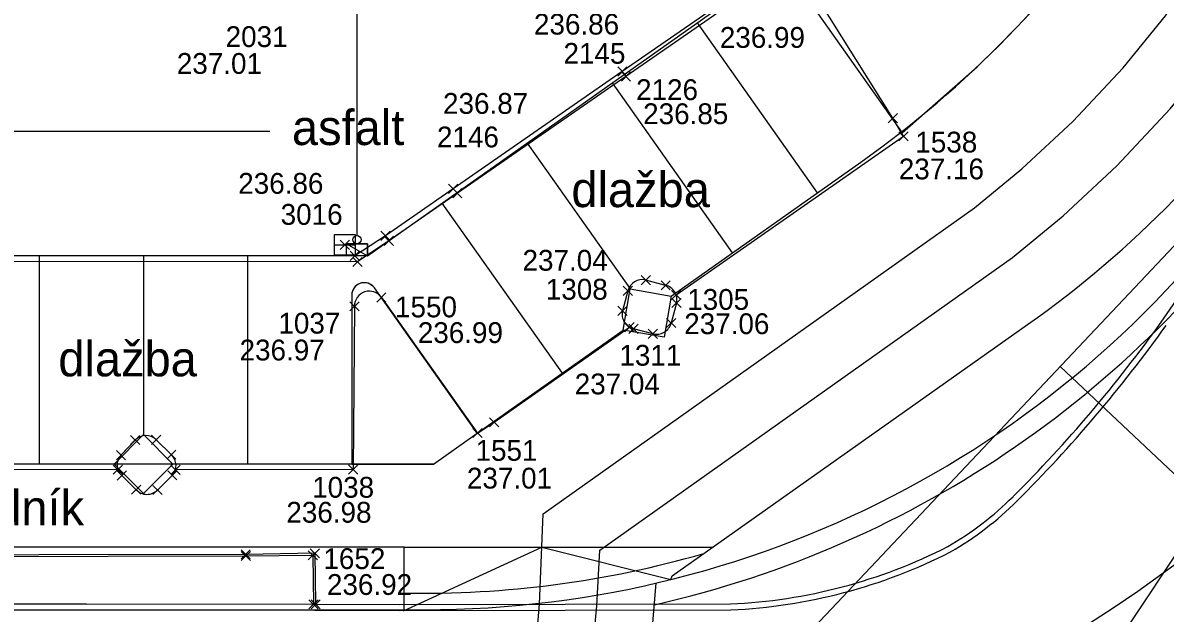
# Model space of a CAD drawing. Extents: x -264165 to -263733, y -1242319 to -1242245.
# Drawn here: x -263825.46 to -263798.04, y -1242301.57 to -1242287.38 of the extents above; entities that cross this region are included whole.
import ezdxf

# ---------------------------------------------------------------- set-up
doc = ezdxf.new("R2010")
doc.units = 0
for name, color, linetype in [('KFA_BOD_CISLO', 7, 'Continuous'), ('KFA_BOD_SYMBOL', 7, 'Continuous'), ('KFA_BOD_VYSKA', 7, 'Continuous'), ('KFA_SO_20-2_OBRUBNIKY_DOLNA_HRANA', 7, 'Continuous'), ('KFA_SO_20-2_OBRUBNIKY_HORNA_HRANA', 7, 'Continuous'), ('KFA_UV_BOD_CISLO', 7, 'Continuous'), ('KFA_UV_BOD_SYMBOL', 7, 'Continuous'), ('KFA_UV_BOD_VYSKA', 7, 'Continuous'), ('POPIS', 7, 'Continuous'), ('PROJEKT_OBRUBNIKY_KOMUNIKACIE', 7, 'Continuous'), ('PROJEKT_TDZ_VODOROVNE', 7, 'Continuous'), ('SITUACIA_DSP_2D', 7, 'Continuous'), ('SO_20-1_OBRUBNIKY_DOLNA_HRANA', 7, 'Continuous'), ('SO_20-1_OBRUBNIKY_HORNA_HRANA', 7, 'Continuous'), ('ULICNA_VPUST_POKLOP', 7, 'Continuous')]:
    doc.layers.add(name, color=color, linetype=linetype)

msp = doc.modelspace()

# ---------------------------------------------------------------- linework, layer by layer
at = {"layer": 'KFA_BOD_SYMBOL'}
for p, q in [((-263811.183, -1242288.666), (-263810.962, -1242288.444)), ((-263810.962, -1242288.666), (-263811.183, -1242288.444)), ((-263811.095, -1242288.784), (-263810.875, -1242288.562)), ((-263810.875, -1242288.784), (-263811.095, -1242288.562)), ((-263804.688, -1242289.786), (-263804.467, -1242289.566)), ((-263804.467, -1242289.786), (-263804.688, -1242289.566)), ((-263804.431, -1242290.221), (-263804.209, -1242289.999)), ((-263804.209, -1242290.221), (-263804.431, -1242289.999)), ((-263815.243, -1242291.48), (-263815.022, -1242291.258)), ((-263815.022, -1242291.48), (-263815.243, -1242291.258)), ((-263815.143, -1242291.589), (-263814.921, -1242291.367)), ((-263814.921, -1242291.589), (-263815.143, -1242291.367)), ((-263816.87, -1242292.612), (-263816.649, -1242292.39)), ((-263816.649, -1242292.612), (-263816.87, -1242292.39)), ((-263816.789, -1242292.73), (-263816.568, -1242292.508)), ((-263816.568, -1242292.73), (-263816.789, -1242292.508)), ((-263817.603, -1242293.093), (-263817.382, -1242292.872)), ((-263817.382, -1242293.093), (-263817.603, -1242292.872)), ((-263817.541, -1242293.24), (-263817.32, -1242293.019)), ((-263817.32, -1242293.24), (-263817.541, -1242293.019)), ((-263810.617, -1242293.674), (-263810.395, -1242293.453)), ((-263810.395, -1242293.674), (-263810.617, -1242293.453)), ((-263810.142, -1242293.802), (-263809.921, -1242293.582)), ((-263809.921, -1242293.802), (-263810.142, -1242293.582)), ((-263811.049, -1242293.934), (-263810.828, -1242293.714)), ((-263810.828, -1242293.934), (-263811.049, -1242293.714)), ((-263809.889, -1242294.032), (-263809.668, -1242293.811)), ((-263809.668, -1242294.032), (-263809.889, -1242293.811)), ((-263817.611, -1242294.303), (-263817.39, -1242294.083)), ((-263817.39, -1242294.303), (-263817.611, -1242294.083)), ((-263816.968, -1242294.092), (-263816.747, -1242293.87)), ((-263816.747, -1242294.092), (-263816.968, -1242293.87)), ((-263809.881, -1242294.225), (-263809.66, -1242294.005)), ((-263809.66, -1242294.225), (-263809.881, -1242294.005)), ((-263811.177, -1242294.416), (-263810.955, -1242294.194)), ((-263810.955, -1242294.416), (-263811.177, -1242294.194)), ((-263811.008, -1242294.808), (-263810.787, -1242294.586)), ((-263810.787, -1242294.808), (-263811.008, -1242294.586)), ((-263810.913, -1242294.845), (-263810.692, -1242294.623)), ((-263810.692, -1242294.845), (-263810.913, -1242294.623)), ((-263810.011, -1242294.704), (-263809.79, -1242294.484)), ((-263809.79, -1242294.704), (-263810.011, -1242294.484)), ((-263810.448, -1242294.964), (-263810.226, -1242294.742)), ((-263810.226, -1242294.964), (-263810.448, -1242294.742)), ((-263814.258, -1242297.092), (-263814.036, -1242296.87)), ((-263814.036, -1242297.092), (-263814.258, -1242296.87)), ((-263814.661, -1242297.349), (-263814.44, -1242297.127)), ((-263814.44, -1242297.349), (-263814.661, -1242297.127)), ((-263822.877, -1242297.516), (-263822.655, -1242297.296)), ((-263822.655, -1242297.516), (-263822.877, -1242297.296)), ((-263822.376, -1242297.512), (-263822.155, -1242297.291)), ((-263822.155, -1242297.512), (-263822.376, -1242297.291)), ((-263823.219, -1242297.88), (-263822.997, -1242297.659)), ((-263822.997, -1242297.88), (-263823.219, -1242297.659)), ((-263822.009, -1242297.869), (-263821.788, -1242297.647)), ((-263821.788, -1242297.869), (-263822.009, -1242297.647)), ((-263823.294, -1242298.228), (-263823.073, -1242298.007)), ((-263823.073, -1242298.228), (-263823.294, -1242298.007)), ((-263823.199, -1242298.372), (-263822.978, -1242298.15)), ((-263822.978, -1242298.372), (-263823.199, -1242298.15)), ((-263821.986, -1242298.366), (-263821.765, -1242298.144)), ((-263821.765, -1242298.366), (-263821.986, -1242298.144)), ((-263821.911, -1242298.231), (-263821.69, -1242298.011)), ((-263821.69, -1242298.231), (-263821.911, -1242298.011)), ((-263817.645, -1242298.225), (-263817.424, -1242298.004)), ((-263817.424, -1242298.225), (-263817.645, -1242298.004)), ((-263822.855, -1242298.71), (-263822.633, -1242298.488)), ((-263822.633, -1242298.71), (-263822.855, -1242298.488)), ((-263822.345, -1242298.718), (-263822.123, -1242298.497)), ((-263822.123, -1242298.718), (-263822.345, -1242298.497)), ((-263820.225, -1242300.264), (-263820.003, -1242300.042)), ((-263820.003, -1242300.264), (-263820.225, -1242300.042)), ((-263820.223, -1242300.303), (-263820.002, -1242300.083)), ((-263820.002, -1242300.303), (-263820.223, -1242300.083)), ((-263818.615, -1242300.288), (-263818.394, -1242300.066)), ((-263818.394, -1242300.288), (-263818.615, -1242300.066)), ((-263818.565, -1242300.238), (-263818.344, -1242300.016)), ((-263818.344, -1242300.238), (-263818.565, -1242300.016)), ((-263818.596, -1242301.463), (-263818.375, -1242301.242)), ((-263818.375, -1242301.463), (-263818.596, -1242301.242)), ((-263818.546, -1242301.463), (-263818.325, -1242301.242)), ((-263818.325, -1242301.463), (-263818.546, -1242301.242))]:
    msp.add_line(p, q, dxfattribs=at)
at = {"layer": 'KFA_SO_20-2_OBRUBNIKY_DOLNA_HRANA'}
for points in [[(-263806.994, -1242271.026), (-263807.002, -1242275.743), (-263807.011, -1242281.745), (-263807.02, -1242285.741), (-263807.029, -1242285.754), (-263811.073, -1242288.555), (-263815.133, -1242291.369), (-263816.759, -1242292.501), (-263817.492, -1242292.982)], [(-263806.84, -1242270.884), (-263806.855, -1242275.745), (-263806.866, -1242281.754), (-263806.878, -1242285.825), (-263810.985, -1242288.673), (-263815.032, -1242291.478), (-263816.678, -1242292.619), (-263817.431, -1242293.129)], [(-263817.492, -1242292.982), (-263829.632, -1242292.973), (-263839.651, -1242292.963), (-263849.653, -1242292.97), (-263858.67, -1242292.978), (-263866.671, -1242292.969), (-263877.683, -1242292.971), (-263887.693, -1242292.984), (-263898.705, -1242293.002), (-263909.705, -1242293.003), (-263917.41, -1242292.997)], [(-263817.431, -1242293.129), (-263829.63, -1242293.121), (-263839.649, -1242293.107), (-263849.656, -1242293.117), (-263858.667, -1242293.124), (-263866.668, -1242293.115), (-263877.682, -1242293.116), (-263887.695, -1242293.128), (-263898.705, -1242293.142), (-263909.706, -1242293.151), (-263917.057, -1242293.143)]]:
    msp.add_lwpolyline(points, dxfattribs=at)
at = {"layer": 'KFA_SO_20-2_OBRUBNIKY_HORNA_HRANA'}
for p, q in [((-263810.031, -1242293.692), (-263810.506, -1242293.563)), ((-263810.938, -1242293.824), (-263811.066, -1242294.305)), ((-263809.77, -1242294.115), (-263809.9, -1242294.594)), ((-263810.337, -1242294.853), (-263810.802, -1242294.734)), ((-263822.766, -1242297.406), (-263823.108, -1242297.769)), ((-263821.899, -1242297.758), (-263822.265, -1242297.401)), ((-263823.183, -1242298.117), (-263829.355, -1242298.13)), ((-263823.089, -1242298.261), (-263822.744, -1242298.599)), ((-263821.876, -1242298.255), (-263822.234, -1242298.607)), ((-263818.454, -1242300.127), (-263818.436, -1242301.352)), ((-263818.504, -1242300.177), (-263818.486, -1242301.352))]:
    msp.add_line(p, q, dxfattribs=at)
for points in [[(-263809.779, -1242293.921), (-263804.32, -1242290.11), (-263804.578, -1242289.676), (-263806.686, -1242286.292)], [(-263816.857, -1242293.981), (-263814.551, -1242297.238), (-263814.147, -1242296.981), (-263810.898, -1242294.697)], [(-263817.501, -1242294.193), (-263817.535, -1242298.114), (-263821.801, -1242298.121)], [(-263818.454, -1242300.127), (-263820.114, -1242300.153), (-263830.062, -1242300.171), (-263840.06, -1242300.171), (-263850.054, -1242300.16), (-263860.027, -1242300.174), (-263870.031, -1242300.18), (-263880.008, -1242300.187), (-263888.684, -1242300.195), (-263899.013, -1242300.19), (-263908.987, -1242300.212), (-263915.978, -1242300.22), (-263917.721, -1242300.207)], [(-263818.504, -1242300.177), (-263820.112, -1242300.193), (-263830.062, -1242300.221), (-263840.06, -1242300.221), (-263850.054, -1242300.21), (-263860.027, -1242300.224), (-263870.031, -1242300.23), (-263880.008, -1242300.237), (-263888.684, -1242300.245), (-263899.013, -1242300.24), (-263908.987, -1242300.262), (-263915.978, -1242300.27), (-263917.654, -1242300.257)]]:
    msp.add_lwpolyline(points, dxfattribs=at)
for centre, major_axis, ratio, start_param, end_param in [((-263810.591, -1242293.91), (-0.323, -0.152), 0.999281, 4.032527, 5.601655), ((-263817.147, -1242294.184), (0.049, -0.351), 0.999595, 2.042666, 4.598058), ((-263810.111, -1242294.033), (-0.104, 0.335), 0.999708, 4.176421, 5.753618), ((-263810.725, -1242294.391), (-0.16, -0.313), 0.999933, 4.9388, 6.536829), ((-263810.245, -1242294.51), (-0.245, -0.257), 0.998318, 0.49947, 2.091931), ((-263822.513, -1242297.657), (-0.356, 0.021), 0.998304, 4.002686, 5.559324), ((-263822.855, -1242298.006), (0.013, -0.347), 0.998277, 3.923315, 5.501463), ((-263822.142, -1242298.018), (-0.141, 0.327), 0.999984, 3.579828, 5.12581), ((-263822.485, -1242298.356), (0.309, -0.176), 0.999327, 4.412509, 6.015834)]:
    msp.add_ellipse(centre, major_axis=major_axis, ratio=ratio, start_param=start_param, end_param=end_param, dxfattribs=at)
at = {"layer": 'KFA_UV_BOD_SYMBOL'}
for p, q in [((-263817.846, -1242292.829), (-263817.625, -1242292.608)), ((-263817.625, -1242292.829), (-263817.846, -1242292.608))]:
    msp.add_line(p, q, dxfattribs=at)
at = {"layer": 'PROJEKT_OBRUBNIKY_KOMUNIKACIE'}
for p, q in [((-263817.19, -1242292.982), (-263807.068, -1242285.823)), ((-263809.895, -1242293.947), (-263805.344, -1242290.728)), ((-263817.19, -1242292.982), (-263917.08, -1242292.982)), ((-263817.545, -1242293.812), (-263817.562, -1242293.868)), ((-263817.518, -1242293.761), (-263817.545, -1242293.812)), ((-263817.482, -1242293.716), (-263817.518, -1242293.761)), ((-263817.437, -1242293.678), (-263817.482, -1242293.716)), ((-263817.386, -1242293.65), (-263817.437, -1242293.678)), ((-263817.33, -1242293.633), (-263817.386, -1242293.65)), ((-263817.273, -1242293.626), (-263817.33, -1242293.633)), ((-263817.215, -1242293.631), (-263817.273, -1242293.626)), ((-263817.159, -1242293.647), (-263817.215, -1242293.631)), ((-263817.107, -1242293.673), (-263817.159, -1242293.647)), ((-263817.061, -1242293.709), (-263817.107, -1242293.673)), ((-263817.023, -1242293.753), (-263817.061, -1242293.709)), ((-263814.555, -1242297.242), (-263817.023, -1242293.753)), ((-263817.562, -1242293.868), (-263817.568, -1242293.926)), ((-263817.568, -1242293.926), (-263817.568, -1242297.982)), ((-263809.875, -1242300.669), (-263801.342, -1242294.634)), ((-263814.555, -1242297.242), (-263811.05, -1242294.763)), ((-263815.601, -1242297.982), (-263814.555, -1242297.242)), ((-263815.601, -1242297.982), (-263917.08, -1242297.982)), ((-263817.568, -1242297.982), (-263815.601, -1242297.982)), ((-263816.308, -1242299.982), (-263918.049, -1242299.982)), ((-263816.308, -1242301.482), (-263816.308, -1242299.982)), ((-263816.308, -1242299.982), (-263808.904, -1242299.982)), ((-263809.906, -1242300.757), (-263809.875, -1242300.669)), ((-263914.08, -1242301.482), (-263815.822, -1242301.482))]:
    msp.add_line(p, q, dxfattribs=at)
for points in [[(-263806.901, -1242286.416), (-263804.349, -1242290.024), (-263802.552, -1242288.44)], [(-263810.881, -1242293.778), (-263809.895, -1242293.947), (-263810.064, -1242294.932), (-263811.05, -1242294.763), (-263810.881, -1242293.778)], [(-263822.568, -1242297.275), (-263821.861, -1242297.982), (-263822.568, -1242298.689), (-263823.275, -1242297.982), (-263822.568, -1242297.275)], [(-263816.327, -1242301.51), (-263813.002, -1242299.982), (-263809.906, -1242300.757)]]:
    msp.add_lwpolyline(points, dxfattribs=at)
for centre, radius, start, end in [((-263821.806, -1242268.304), 27.86, 313.7192, 328.4502), ((-263820.069, -1242269.909), 25.5, 305.2702, 326.1165), ((-263816.067, -1242273.815), 25.5, 305.2702, 326.1165), ((-263815.822, -1242276.982), 24.5, 270, 326.3992)]:
    msp.add_arc(centre, radius, start, end, dxfattribs=at)
at = {"layer": 'PROJEKT_TDZ_VODOROVNE'}
for p, q in [((-263809.278, -1242287.386), (-263806.39, -1242291.468)), ((-263811.319, -1242288.829), (-263808.432, -1242292.912)), ((-263819.531, -1242289.994), (-263917.477, -1242289.994)), ((-263813.36, -1242290.273), (-263810.881, -1242293.778)), ((-263813.36, -1242290.273), (-263810.881, -1242293.778)), ((-263815.401, -1242291.717), (-263812.514, -1242295.799)), ((-263825.068, -1242297.982), (-263825.068, -1242292.982)), ((-263822.568, -1242292.982), (-263822.568, -1242297.275)), ((-263820.068, -1242292.982), (-263820.068, -1242297.982)), ((-263810.915, -1242308.545), (-263810.255, -1242300.841))]:
    msp.add_line(p, q, dxfattribs=at)
for points in [[(-263816.072, -1242319.185), (-263814.291, -1242315.804), (-263813.06, -1242301.353), (-263812.968, -1242299.181), (-263802.618, -1242291.831), (-263801.478, -1242290.893), (-263800.257, -1242289.755), (-263799.049, -1242288.464), (-263798.027, -1242287.218), (-263780.363, -1242261.313)], [(-263814.635, -1242319.185), (-263813.062, -1242316.188), (-263811.682, -1242301.389), (-263811.608, -1242300.055), (-263801.705, -1242293.023), (-263800.489, -1242292.021), (-263799.197, -1242290.817), (-263797.92, -1242289.454), (-263796.825, -1242288.118), (-263780.363, -1242263.975)]]:
    msp.add_lwpolyline(points, dxfattribs=at)
for centre, radius, start, end in [((-263815.822, -1242276.982), 25, 282.7622, 326.3992), ((-263816.477, -1242275.476), 31.135, 289.1139, 310.0684), ((-263809.228, -1242287.295), 24, 270.4085, 326.3969)]:
    msp.add_arc(centre, radius, start, end, dxfattribs=at)
at = {"layer": 'SITUACIA_DSP_2D'}
for p, q in [((-263810.431, -1242319.185), (-263780.363, -1242273.949)), ((-263780.363, -1242274.247), (-263808.248, -1242303.783)), ((-263817.441, -1242292.492), (-263817.441, -1242284.482)), ((-263809.895, -1242293.947), (-263805.344, -1242290.728)), ((-263817.691, -1242292.692), (-263817.191, -1242292.692)), ((-263817.691, -1242292.982), (-263817.691, -1242292.692)), ((-263817.691, -1242292.692), (-263817.191, -1242292.982)), ((-263817.691, -1242292.692), (-263817.191, -1242292.982)), ((-263817.191, -1242292.692), (-263817.691, -1242292.692)), ((-263817.191, -1242292.692), (-263817.191, -1242292.982)), ((-263817.191, -1242292.982), (-263817.191, -1242292.692)), ((-263817.191, -1242292.982), (-263817.691, -1242292.982)), ((-263809.875, -1242300.669), (-263801.342, -1242294.634)), ((-263814.555, -1242297.242), (-263811.05, -1242294.763)), ((-263797.048, -1242298.952), (-263800.558, -1242295.638)), ((-263815.601, -1242297.982), (-263917.08, -1242297.982)), ((-263816.308, -1242299.982), (-263918.049, -1242299.982)), ((-263816.308, -1242301.482), (-263816.308, -1242299.982)), ((-263816.308, -1242299.982), (-263808.904, -1242299.982)), ((-263809.906, -1242300.757), (-263809.875, -1242300.669)), ((-263914.08, -1242301.482), (-263815.822, -1242301.482))]:
    msp.add_line(p, q, dxfattribs=at)
for points in [[(-263806.901, -1242286.416), (-263804.349, -1242290.024), (-263802.552, -1242288.44)], [(-263817.568, -1242293.926), (-263817.568, -1242297.982), (-263815.601, -1242297.982), (-263814.555, -1242297.242), (-263817.023, -1242293.753)], [(-263816.327, -1242301.51), (-263813.002, -1242299.982), (-263809.906, -1242300.757)]]:
    msp.add_lwpolyline(points, dxfattribs=at)
for points in [[(-263810.881, -1242293.778), (-263809.895, -1242293.947), (-263810.064, -1242294.932), (-263811.05, -1242294.763)], [(-263822.568, -1242297.275), (-263821.861, -1242297.982), (-263822.568, -1242298.689), (-263823.275, -1242297.982)]]:
    msp.add_lwpolyline(points, close=True, dxfattribs=at)
msp.add_circle((-263817.441, -1242292.592), 0.1, dxfattribs=at)
for centre, radius, start, end in [((-263821.806, -1242268.304), 27.86, 313.7192, 328.4502), ((-263820.069, -1242269.909), 25.5, 305.2702, 326.1165), ((-263816.067, -1242273.815), 25.5, 305.2702, 326.1165), ((-263815.822, -1242276.982), 24.5, 270, 326.3992), ((-263817.268, -1242293.926), 0.3, 35.2702, 180), ((-263815.836, -1242276.967), 24.119, 268.8787, 286.1798)]:
    msp.add_arc(centre, radius, start, end, dxfattribs=at)
at = {"layer": 'SO_20-1_OBRUBNIKY_DOLNA_HRANA'}
for points in [[(-263913.884, -1242301.489), (-263907.893, -1242301.489), (-263900.89, -1242301.488), (-263893.898, -1242301.483), (-263886.917, -1242301.473), (-263879.922, -1242301.465), (-263872.91, -1242301.469), (-263865.929, -1242301.465), (-263859.932, -1242301.473), (-263850.941, -1242301.471), (-263843.947, -1242301.471), (-263836.942, -1242301.481), (-263829.943, -1242301.484), (-263823.945, -1242301.487), (-263818.452, -1242301.495), (-263816.42, -1242301.504)], [(-263816.42, -1242301.504), (-263808.465, -1242301.488)]]:
    msp.add_lwpolyline(points, dxfattribs=at)
for centre, major_axis, ratio, start_param, end_param in [((-263825.45, -1242274.928), (18.854, 28.266), 0.994545, 4.514508, 4.677485), ((-263807.174, -1242293.246), (7.914, -0.383), 0.999893, 5.287754, 5.542292), ((-263809.043, -1242288.645), (12.659, 2.536), 0.995625, 4.560279, 4.986171)]:
    msp.add_ellipse(centre, major_axis=major_axis, ratio=ratio, start_param=start_param, end_param=end_param, dxfattribs=at)
at = {"layer": 'SO_20-1_OBRUBNIKY_HORNA_HRANA'}
for points in [[(-263798.132, -1242294.573), (-263796.423, -1242292.099), (-263795.31, -1242290.444), (-263793.659, -1242287.955), (-263790.34, -1242282.948), (-263787.584, -1242278.79), (-263784.82, -1242274.623)], [(-263913.884, -1242301.344), (-263907.893, -1242301.343), (-263900.896, -1242301.344), (-263893.895, -1242301.338), (-263886.916, -1242301.328), (-263879.921, -1242301.324), (-263872.911, -1242301.324), (-263865.928, -1242301.325), (-263859.931, -1242301.327), (-263850.935, -1242301.324), (-263843.941, -1242301.331), (-263836.939, -1242301.332), (-263829.941, -1242301.342), (-263823.94, -1242301.343), (-263818.456, -1242301.352), (-263816.413, -1242301.358)], [(-263816.413, -1242301.358), (-263808.476, -1242301.344)]]:
    msp.add_lwpolyline(points, dxfattribs=at)
for centre, major_axis, ratio, start_param, end_param in [((-263824.958, -1242275.34), (19.218, 27.206), 0.990974, 4.5401, 4.705457), ((-263807.23, -1242293.156), (3.846, 6.885), 0.999705, 4.179295, 4.429956), ((-263809.03, -1242288.701), (12.476, 2.408), 0.995918, 4.56612, 4.994215)]:
    msp.add_ellipse(centre, major_axis=major_axis, ratio=ratio, start_param=start_param, end_param=end_param, dxfattribs=at)
at = {"layer": 'ULICNA_VPUST_POKLOP'}
msp.add_line((-263817.735, -1242292.719), (-263817.735, -1242292.719), dxfattribs=at)
msp.add_lwpolyline([(-263817.985, -1242292.719), (-263817.985, -1242292.469), (-263817.485, -1242292.469), (-263817.485, -1242292.969), (-263817.985, -1242292.969), (-263817.985, -1242292.719), (-263817.485, -1242292.719)], dxfattribs=at)

# ---------------------------------------------------------------- texts
at = {"layer": 'KFA_BOD_CISLO'}
for s, p in [('2031', (-263820.596, -1242287.966)), ('2145', (-263812.484, -1242288.367)), ('2126', (-263810.741, -1242289.24)), ('2146', (-263815.522, -1242290.376)), ('1538', (-263804.037, -1242290.499)), ('1308', (-263812.909, -1242294.034)), ('1305', (-263809.514, -1242294.279)), ('1550', (-263816.529, -1242294.459)), ('1037', (-263819.329, -1242294.849)), ('1311', (-263811.142, -1242295.62)), ('1551', (-263814.595, -1242297.905)), ('1038', (-263818.518, -1242298.792)), ('1652', (-263818.248, -1242300.505))]:
    msp.add_text(s, height=0.5, dxfattribs=at).set_placement(p)
at = {"layer": 'KFA_BOD_VYSKA'}
for s, p in [('236.86', (-263813.193, -1242287.666)), ('236.99', (-263808.731, -1242287.985)), ('237.01', (-263821.768, -1242288.61)), ('236.87', (-263815.376, -1242289.57)), ('236.85', (-263810.572, -1242289.818)), ('237.16', (-263804.434, -1242291.144)), ('237.04', (-263813.468, -1242293.339)), ('237.06', (-263809.585, -1242294.862)), ('236.99', (-263815.982, -1242295.076)), ('236.97', (-263820.261, -1242295.494)), ('237.04', (-263812.214, -1242296.309)), ('237.01', (-263814.803, -1242298.572)), ('236.98', (-263819.138, -1242299.392)), ('236.92', (-263818.163, -1242301.127))]:
    msp.add_text(s, height=0.5, dxfattribs=at).set_placement(p)
at = {"layer": 'KFA_UV_BOD_CISLO'}
msp.add_text('3016', height=0.5, dxfattribs=at).set_placement((-263819.275, -1242292.236))
at = {"layer": 'KFA_UV_BOD_VYSKA'}
msp.add_text('236.86', height=0.5, dxfattribs=at).set_placement((-263820.293, -1242291.491))
at = {"layer": 'POPIS'}
for s, p in [('asfalt', (-263819.003, -1242290.32)), ('dlažba', (-263812.294, -1242291.811)), ('dlažba', (-263824.612, -1242295.876)), ('chodník', (-263827.947, -1242299.456))]:
    msp.add_text(s, height=0.8438, dxfattribs=at).set_placement(p)

doc.saveas('drawing.dxf')
